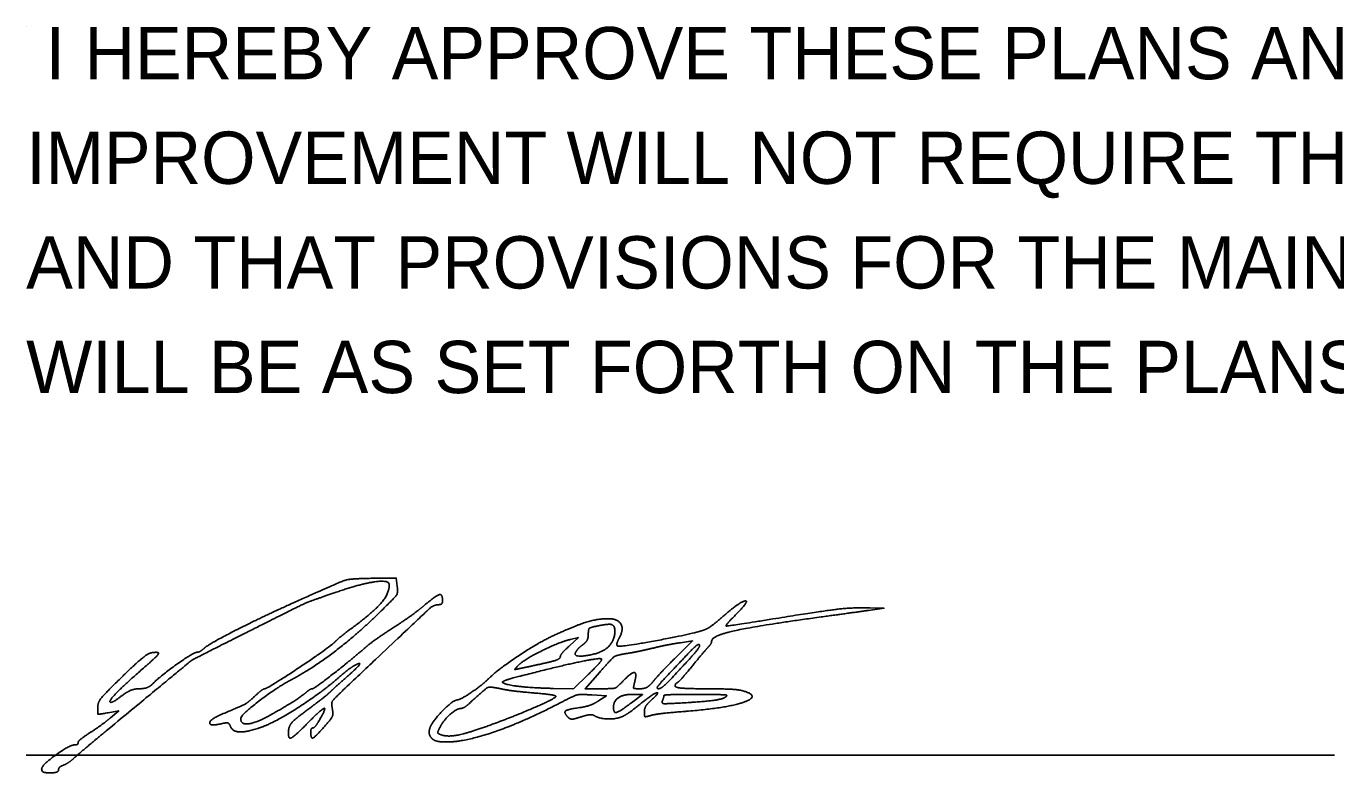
# Model space of a CAD drawing. Extents: x 21.4 to 65.3, y 4 to 26.
# Drawn here: x 45.975 to 49.479, y 12.833 to 14.831 of the extents above; entities that cross this region are included whole.
import ezdxf

# ---------------------------------------------------------------- set-up
doc = ezdxf.new("R2010")
doc.units = 0
doc.layers.add('SH_Data', color=7, linetype='Continuous')
doc.layers.add('SH_Text', color=7, linetype='Continuous')

msp = doc.modelspace()

# ---------------------------------------------------------------- linework, layer by layer
at = {"layer": 'SH_Data'}
for p, q in [((45.9752, 14.8292), (45.9752, 14.8292)), ((45.9752, 12.8804), (49.4752, 12.8804))]:
    msp.add_line(p, q, dxfattribs=at)
at = {"layer": 'SH_Text'}
msp.add_line((46.0166, 12.8433), (46.0166, 12.8433), dxfattribs=at)
for points in [[(46.9679, 13.3325), (46.9654, 13.3544), (46.9054, 13.3537)], [(48.2291, 13.2678), (48.2704, 13.2736), (48.2327, 13.2746)], [(47.4305, 13.1897), (47.4529, 13.1951), (47.4285, 13.1728)], [(47.7254, 13.1813), (47.758, 13.186), (47.7142, 13.1426)], [(47.4789, 13.0961), (47.4397, 13.0581), (47.3863, 13.059)], [(47.5116, 13.0581), (47.4707, 13.0581), (47.5099, 13.1027)], [(47.4882, 13.0416), (47.5274, 13.0394), (47.506, 13.0254)], [(47.5992, 13.0431), (47.6243, 13.0431), (47.5948, 13.0208)], [(46.1947, 12.9939), (46.2229, 12.9989), (46.2004, 12.98)]]:
    msp.add_lwpolyline(points, dxfattribs=at)
for points in [[(46.9054, 13.3537), (46.8429, 13.353), (46.8165, 13.3448), (46.6804, 13.2836)], [(46.5979, 13.2254), (46.71, 13.2817), (46.7357, 13.2929), (46.8079, 13.3176)], [(46.8079, 13.3176), (46.8719, 13.3395), (46.9466, 13.3495), (46.9466, 13.3362)], [(46.9466, 13.3362), (46.9466, 13.3122), (46.9016, 13.2609), (46.8424, 13.2173)], [(46.9078, 13.25), (46.9618, 13.3024), (46.97, 13.3137), (46.9679, 13.3325)], [(46.6804, 13.2836), (46.6002, 13.2476), (46.4643, 13.178), (46.451, 13.1662)], [(46.8228, 13.0539), (47.0442, 13.2635), (47.0661, 13.2831), (47.0797, 13.2831)], [(47.0398, 13.2807), (47.0236, 13.267), (46.9867, 13.2405), (46.9579, 13.2219)], [(47.0891, 13.2944), (47.0891, 13.3124), (47.0715, 13.3075), (47.0398, 13.2807)], [(47.0797, 13.2831), (47.0849, 13.2831), (47.0891, 13.2882), (47.0891, 13.2944)], [(47.8759, 13.2587), (47.9127, 13.2956), (47.8832, 13.2902), (47.8403, 13.2523)], [(46.6845, 13.0821), (46.7382, 13.1105), (46.8529, 13.1968), (46.9078, 13.25)], [(47.5317, 13.2456), (47.5042, 13.2456), (47.4424, 13.2265), (47.3869, 13.2008)], [(47.5618, 13.1934), (47.5746, 13.2173), (47.5583, 13.2456), (47.5317, 13.2456)], [(47.8403, 13.2523), (47.8211, 13.2353), (47.7986, 13.219), (47.7904, 13.2159)], [(47.8091, 13.1852), (47.8091, 13.1997), (47.9317, 13.2269), (48.1024, 13.2503)], [(47.9726, 13.2448), (47.8523, 13.2253), (47.8437, 13.2265), (47.8759, 13.2587)], [(48.2327, 13.2746), (48.1883, 13.2758), (48.1043, 13.2661), (47.9726, 13.2448)], [(48.1024, 13.2503), (48.1494, 13.2567), (48.2064, 13.2646), (48.2291, 13.2678)], [(46.1891, 12.9451), (46.4137, 13.1311), (46.4233, 13.1377), (46.5979, 13.2254)], [(46.8424, 13.2173), (46.8276, 13.2064), (46.8094, 13.1915), (46.8021, 13.1842)], [(46.9579, 13.2219), (46.929, 13.2032), (46.8952, 13.1793), (46.8829, 13.1686)], [(47.4791, 13.2038), (47.4791, 13.2173), (47.4844, 13.2223), (47.5026, 13.2259)], [(47.5026, 13.2259), (47.5154, 13.2285), (47.5306, 13.2306), (47.5363, 13.2306)], [(47.5363, 13.2306), (47.5513, 13.2306), (47.5493, 13.1878), (47.5335, 13.1711)], [(47.7904, 13.2159), (47.763, 13.2058), (47.5613, 13.1684), (47.557, 13.1727)], [(46.8021, 13.1842), (46.7873, 13.1694), (46.6206, 13.0581), (46.6132, 13.0581)], [(47.3869, 13.2008), (47.3449, 13.1813), (47.2364, 13.109), (47.2107, 13.0833)], [(47.2916, 13.1204), (47.306, 13.1353), (47.4011, 13.1828), (47.4305, 13.1897)], [(47.4458, 13.1566), (47.4492, 13.1623), (47.4581, 13.1713), (47.4655, 13.1767)], [(47.4655, 13.1767), (47.473, 13.182), (47.4791, 13.1943), (47.4791, 13.2038)], [(47.557, 13.1727), (47.5548, 13.1749), (47.5569, 13.1843), (47.5618, 13.1934)], [(47.6516, 13.1667), (47.6743, 13.1721), (47.7075, 13.1787), (47.7254, 13.1813)], [(47.7761, 13.1761), (47.7796, 13.1726), (47.7558, 13.1437), (47.7031, 13.0873)], [(47.7515, 13.1575), (47.7631, 13.1697), (47.7742, 13.178), (47.7761, 13.1761)], [(47.7997, 13.1693), (47.8049, 13.1747), (47.8091, 13.1819), (47.8091, 13.1852)], [(46.3095, 13.1542), (46.3014, 13.1529), (46.266, 13.1236), (46.2307, 13.089)], [(46.2997, 13.1227), (46.3275, 13.1469), (46.3308, 13.1577), (46.3095, 13.1542)], [(46.4319, 13.1556), (46.4232, 13.1556), (46.3335, 13.0918), (46.3144, 13.072)], [(46.451, 13.1662), (46.4445, 13.1604), (46.4359, 13.1556), (46.4319, 13.1556)], [(46.8829, 13.1686), (46.8382, 13.1302), (46.7455, 13.0581), (46.7408, 13.0581)], [(47.4041, 13.143), (47.4041, 13.1389), (47.3847, 13.1313), (47.361, 13.1262)], [(47.4285, 13.1728), (47.4151, 13.1605), (47.4041, 13.1471), (47.4041, 13.143)], [(47.5335, 13.1711), (47.5171, 13.1539), (47.4361, 13.1405), (47.4458, 13.1566)], [(47.5099, 13.1027), (47.5423, 13.1394), (47.5545, 13.1481), (47.5798, 13.152)], [(47.5798, 13.152), (47.5966, 13.1547), (47.6289, 13.1613), (47.6516, 13.1667)], [(47.7142, 13.1426), (47.6901, 13.1188), (47.6628, 13.09), (47.6535, 13.0787)], [(47.667, 13.0581), (47.6591, 13.0581), (47.6805, 13.0833), (47.7515, 13.1575)], [(47.7566, 13.1181), (47.7751, 13.1408), (47.7945, 13.1638), (47.7997, 13.1693)], [(46.1997, 13.0225), (46.196, 13.0262), (46.2429, 13.0732), (46.2997, 13.1227)], [(46.8116, 13.0883), (46.8261, 13.101), (46.8442, 13.1149), (46.8519, 13.1193)], [(46.8519, 13.1193), (46.8727, 13.1309), (46.8601, 13.1131), (46.8275, 13.0849)], [(47.2991, 13.1128), (47.2823, 13.1092), (47.2815, 13.1099), (47.2916, 13.1204)], [(47.361, 13.1262), (47.3373, 13.121), (47.3094, 13.115), (47.2991, 13.1128)], [(47.3044, 13.0938), (47.4012, 13.1186), (47.5107, 13.1415), (47.5145, 13.1377)], [(47.5145, 13.1377), (47.5165, 13.1357), (47.5005, 13.117), (47.4789, 13.0961)], [(47.7172, 13.0744), (47.7203, 13.0757), (47.738, 13.0954), (47.7566, 13.1181)], [(46.2307, 13.089), (46.1843, 13.0435), (46.1666, 13.021), (46.1666, 13.0075)], [(46.3144, 13.072), (46.3071, 13.0644), (46.2908, 13.0581), (46.2783, 13.0581)], [(46.5491, 12.9781), (46.5491, 12.9876), (46.6449, 13.0612), (46.6845, 13.0821)], [(46.6024, 12.9544), (46.6394, 12.9672), (46.766, 13.0482), (46.8116, 13.0883)], [(46.8275, 13.0849), (46.8129, 13.0722), (46.7953, 13.0564), (46.7884, 13.0496)], [(47.2107, 13.0833), (47.1954, 13.068), (47.1361, 13.0281), (47.1286, 13.0281)], [(47.2495, 13.0752), (47.2476, 13.0772), (47.2722, 13.0855), (47.3044, 13.0938)], [(47.3863, 13.059), (47.331, 13.06), (47.2558, 13.0689), (47.2495, 13.0752)], [(47.5702, 13.0767), (47.5556, 13.0613), (47.5454, 13.0581), (47.5116, 13.0581)], [(47.6035, 13.0769), (47.6097, 13.1016), (47.5937, 13.1015), (47.5702, 13.0767)], [(47.6178, 13.0581), (47.6013, 13.0581), (47.5994, 13.0606), (47.6035, 13.0769)], [(47.6535, 13.0787), (47.6433, 13.0661), (47.6293, 13.0581), (47.6178, 13.0581)], [(47.7031, 13.0873), (47.6881, 13.0712), (47.6719, 13.0581), (47.667, 13.0581)], [(47.7116, 13.065), (47.7116, 13.0688), (47.7141, 13.073), (47.7172, 13.0744)], [(46.2297, 13.0383), (46.2154, 13.0274), (46.2019, 13.0203), (46.1997, 13.0225)], [(46.2783, 13.0581), (46.2653, 13.0581), (46.2445, 13.0496), (46.2297, 13.0383)], [(46.5882, 13.0394), (46.569, 13.0215), (46.5546, 13.0136), (46.4985, 12.9898)], [(46.6132, 13.0581), (46.6106, 13.0581), (46.5994, 13.0497), (46.5882, 13.0394)], [(46.7269, 13.0505), (46.7123, 13.0382), (46.6645, 13.0077), (46.6277, 12.9872)], [(46.7408, 13.0581), (46.7382, 13.0581), (46.7319, 13.0547), (46.7269, 13.0505)], [(46.7884, 13.0496), (46.7816, 13.0429), (46.7571, 13.0235), (46.734, 13.0064)], [(46.7943, 13.0043), (46.7914, 13.0196), (46.7972, 13.0297), (46.8228, 13.0539)], [(47.1608, 13.0188), (47.205, 13.0591), (47.2159, 13.0642), (47.2447, 13.058)], [(47.3916, 13.0361), (47.3822, 13.028), (47.2802, 12.9841), (47.2166, 12.9608)], [(47.2447, 13.058), (47.2602, 13.0547), (47.301, 13.0496), (47.3354, 13.0467)], [(47.3354, 13.0467), (47.3698, 13.0438), (47.3951, 13.039), (47.3916, 13.0361)], [(47.4059, 13.0214), (47.4408, 13.0396), (47.4564, 13.0435), (47.4882, 13.0416)], [(47.5466, 13.0082), (47.5466, 13.0256), (47.573, 13.0431), (47.5992, 13.0431)], [(47.6201, 13.0187), (47.6527, 13.045), (47.672, 13.0496), (47.6442, 13.0244)], [(47.6778, 13.0268), (47.6799, 13.0323), (47.6816, 13.0382), (47.6816, 13.04)], [(47.6816, 13.04), (47.6816, 13.0417), (47.7213, 13.043), (47.7697, 13.0429)], [(47.7922, 13.058), (47.7479, 13.0581), (47.7116, 13.0612), (47.7116, 13.065)], [(47.7416, 12.9978), (47.8529, 13.0064), (47.9415, 13.0395), (47.89, 13.0533)], [(47.8439, 13.0345), (47.8361, 13.03), (47.7948, 13.0242), (47.7519, 13.0215)], [(47.7697, 13.0429), (47.8368, 13.0427), (47.8545, 13.0407), (47.8439, 13.0345)], [(47.89, 13.0533), (47.8806, 13.0558), (47.8366, 13.0579), (47.7922, 13.058)], [(46.1666, 13.0075), (46.1666, 12.9902), (46.1685, 12.9893), (46.1947, 12.9939)], [(46.734, 13.0064), (46.6941, 12.977), (46.6766, 12.9563), (46.6766, 12.9386)], [(46.7265, 12.9644), (46.7649, 13.0033), (46.779, 13.008), (46.7606, 12.9756)], [(46.774, 12.9579), (46.7917, 12.978), (46.797, 12.9902), (46.7943, 13.0043)], [(47.1286, 13.0281), (47.1177, 13.0281), (47.0606, 12.9697), (47.0553, 12.953)], [(47.0826, 12.9556), (47.0923, 12.9743), (47.1266, 13.0049), (47.1383, 13.0053)], [(47.0997, 12.9156), (47.1493, 12.9156), (47.3086, 12.9707), (47.4059, 13.0214)], [(47.1383, 13.0053), (47.1427, 13.0055), (47.1528, 13.0116), (47.1608, 13.0188)], [(47.4554, 13.0075), (47.4239, 13.0033), (47.4129, 12.9938), (47.4251, 12.9816)], [(47.506, 13.0254), (47.4942, 13.0177), (47.4714, 13.0096), (47.4554, 13.0075)], [(47.5948, 13.0208), (47.5628, 12.9966), (47.5466, 12.9924), (47.5466, 13.0082)], [(47.5729, 12.985), (47.5811, 12.9892), (47.6024, 13.0043), (47.6201, 13.0187)], [(47.6442, 13.0244), (47.6359, 13.0169), (47.6291, 13.0042), (47.6291, 12.9961)], [(47.7519, 13.0215), (47.6883, 13.0176), (47.6746, 13.0186), (47.6778, 13.0268)], [(46.2004, 12.98), (46.188, 12.9696), (46.1635, 12.9519), (46.146, 12.9406)], [(46.4985, 12.9898), (46.4672, 12.9765), (46.4651, 12.9574), (46.4957, 12.9641)], [(46.4957, 12.9641), (46.5113, 12.9676), (46.5184, 12.9657), (46.5217, 12.9572)], [(46.6277, 12.9872), (46.5906, 12.9664), (46.5491, 12.9617), (46.5491, 12.9781)], [(46.7606, 12.9756), (46.7536, 12.9633), (46.7453, 12.9532), (46.7422, 12.9531)], [(47.4251, 12.9816), (47.4303, 12.9764), (47.4413, 12.9768), (47.4595, 12.9828)], [(47.4595, 12.9828), (47.4743, 12.9877), (47.4902, 12.9893), (47.495, 12.9863)], [(47.495, 12.9863), (47.509, 12.9776), (47.5567, 12.9768), (47.5729, 12.985)], [(47.6291, 12.9961), (47.6291, 12.9843), (47.6325, 12.9824), (47.646, 12.9865)], [(47.646, 12.9865), (47.6553, 12.9894), (47.6983, 12.9944), (47.7416, 12.9978)], [(46.1066, 12.8754), (46.1169, 12.8847), (46.1541, 12.9161), (46.1891, 12.9451)], [(46.146, 12.9406), (46.1285, 12.9293), (46.1141, 12.9174), (46.1141, 12.9141)], [(46.5217, 12.9572), (46.5271, 12.9432), (46.5659, 12.9418), (46.6024, 12.9544)], [(46.6766, 12.9386), (46.6766, 12.9224), (46.6941, 12.9314), (46.7265, 12.9644)], [(46.7366, 12.9419), (46.7366, 12.9237), (46.7484, 12.9287), (46.774, 12.9579)], [(46.7422, 12.9531), (46.7391, 12.9531), (46.7366, 12.948), (46.7366, 12.9419)], [(47.0553, 12.953), (47.0526, 12.9444), (47.0544, 12.9325), (47.0594, 12.9265)], [(47.0835, 12.9355), (47.0765, 12.9384), (47.0762, 12.9432), (47.0826, 12.9556)], [(47.2166, 12.9608), (47.1593, 12.9397), (47.1003, 12.9285), (47.0835, 12.9355)], [(46.1065, 12.9081), (46.0923, 12.9081), (46.0166, 12.8535), (46.0166, 12.8433)], [(46.1141, 12.9141), (46.1141, 12.9108), (46.1107, 12.9081), (46.1065, 12.9081)], [(47.0594, 12.9265), (47.0647, 12.9202), (47.0815, 12.9156), (47.0997, 12.9156)], [(46.0747, 12.8535), (46.082, 12.8562), (46.0963, 12.866), (46.1066, 12.8754)], [(46.0166, 12.8433), (46.0166, 12.837), (46.0252, 12.8331), (46.0391, 12.8331)], [(46.0391, 12.8331), (46.0515, 12.8331), (46.0616, 12.8366), (46.0616, 12.8408)], [(46.0616, 12.8408), (46.0616, 12.8451), (46.0675, 12.8508), (46.0747, 12.8535)]]:
    msp.add_open_spline(points, degree=2, dxfattribs=at)

# ---------------------------------------------------------------- texts
at = {"layer": 'SH_Data'}
for s, p in [(' I HEREBY APPROVE THESE PLANS AND DECLARE THAT THE MAKING OF THIS', (45.9752, 14.6892)), ('IMPROVEMENT WILL NOT REQUIRE THE CLOSING TO TRAFFIC OF THE HIGHWAY', (45.9752, 14.4092)), ('AND THAT PROVISIONS FOR THE MAINTENANCE AND SAFETY OF TRAFFIC', (45.9752, 14.1292)), ('WILL BE AS SET FORTH ON THE PLANS AND ESTIMATES.', (45.9752, 13.8492))]:
    msp.add_text(s, height=0.14, dxfattribs=at).set_placement(p)

doc.saveas('drawing.dxf')
